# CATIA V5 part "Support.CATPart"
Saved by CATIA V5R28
Part number: Support
Bounding box of the stored display mesh (mm): x -250 to 250, y -32.5 to 32.5, z -30 to 0
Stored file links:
  C:\Users\Parisa\Desktop\tarah sanat\CAR JACK\Support.CATPart
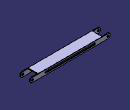
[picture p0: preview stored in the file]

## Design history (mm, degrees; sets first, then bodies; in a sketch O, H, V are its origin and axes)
Body1 (main body)
  Sketch1 on xy-plane, origin (0, 0, 0), H (1, 0, 0), V (0, 1, 0)
    line L1 (200, 27.5) -> (200, -27.5)
    line L2 (200, -27.5) -> (-200, -27.5)
    line L3 (-200, -27.5) -> (-200, 27.5)
    line L4 (-200, 27.5) -> (200, 27.5)
    length L4 = 400
    length L1 = 55
    vertical: L1 V, L3 V
    horizontal: L2 H, L4 H
    equidistance: L1 L3 O, L2 L4 O
  Pad1: profile Sketch1, direction (0, 0, -1), length 5
  Sketch2 on face of Pad1 from Sketch1.L4, origin (0, 27.5, 0), H (-1, 0, 0), V (0, 0, 1)
    construction line L1 (-235, -15) -> (235, -15)
    point P1 (-235, -15)
    point P2 (235, -15)
    line L2 (-235, 0) -> (235, 0)
    line L3 (235, -30) -> (-235, -30)
    arc A1 centre (235, -15) radius 15 from (235, 0) to (235, -30) cw
    arc A2 centre (-235, -15) radius 15 from (-235, -30) to (-235, 0) cw
    reference projected line E1 (-200, 0) -> (200, 0) from edge [face of Pad1 from Sketch1.L4 | start face of Pad1]
    circle A3 centre (235, -15) radius 5
    circle A4 centre (-235, -15) radius 5
    construction line L4 (-150, -15) -> (150, -15)
    point P7 (-150, -15)
    point P8 (150, -15)
    line L5 (-150, -10) -> (150, -10)
    line L6 (150, -20) -> (-150, -20)
    arc A5 centre (150, -15) radius 5 from (150, -10) to (150, -20) cw
    arc A6 centre (-150, -15) radius 5 from (-150, -20) to (-150, -10) cw
    reference projected line E2 (-200, -5) -> (200, -5) from edge [end face of Pad1 | face of Pad1 from Sketch1.L4]
    distance A1 A2 = 500
    distance L2 L3 = 30
    radius A4 = 5
    radius A3 = 5
    distance L5 E2 = 5
    length L5 = 300
    horizontal: L1 H, L4 H
    tangency: A1 L2, A2 L2, A1 L3, A2 L3, A5 L5, A6 L5, A5 L6, A6 L6
    symmetry: P1 P2 V, P7 P8 V
    coincidence: L2 E1, P7 L1
  Pad2: profile Sketch2, direction (0, 1, 0), length 5
  Mirror1: of Pad2, about zx-plane
  AutoFillet1: AutoFilletRadius 1, CurvatureRadius 1, RoundRadius 1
